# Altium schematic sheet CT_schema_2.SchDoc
size 289 x 230 mm
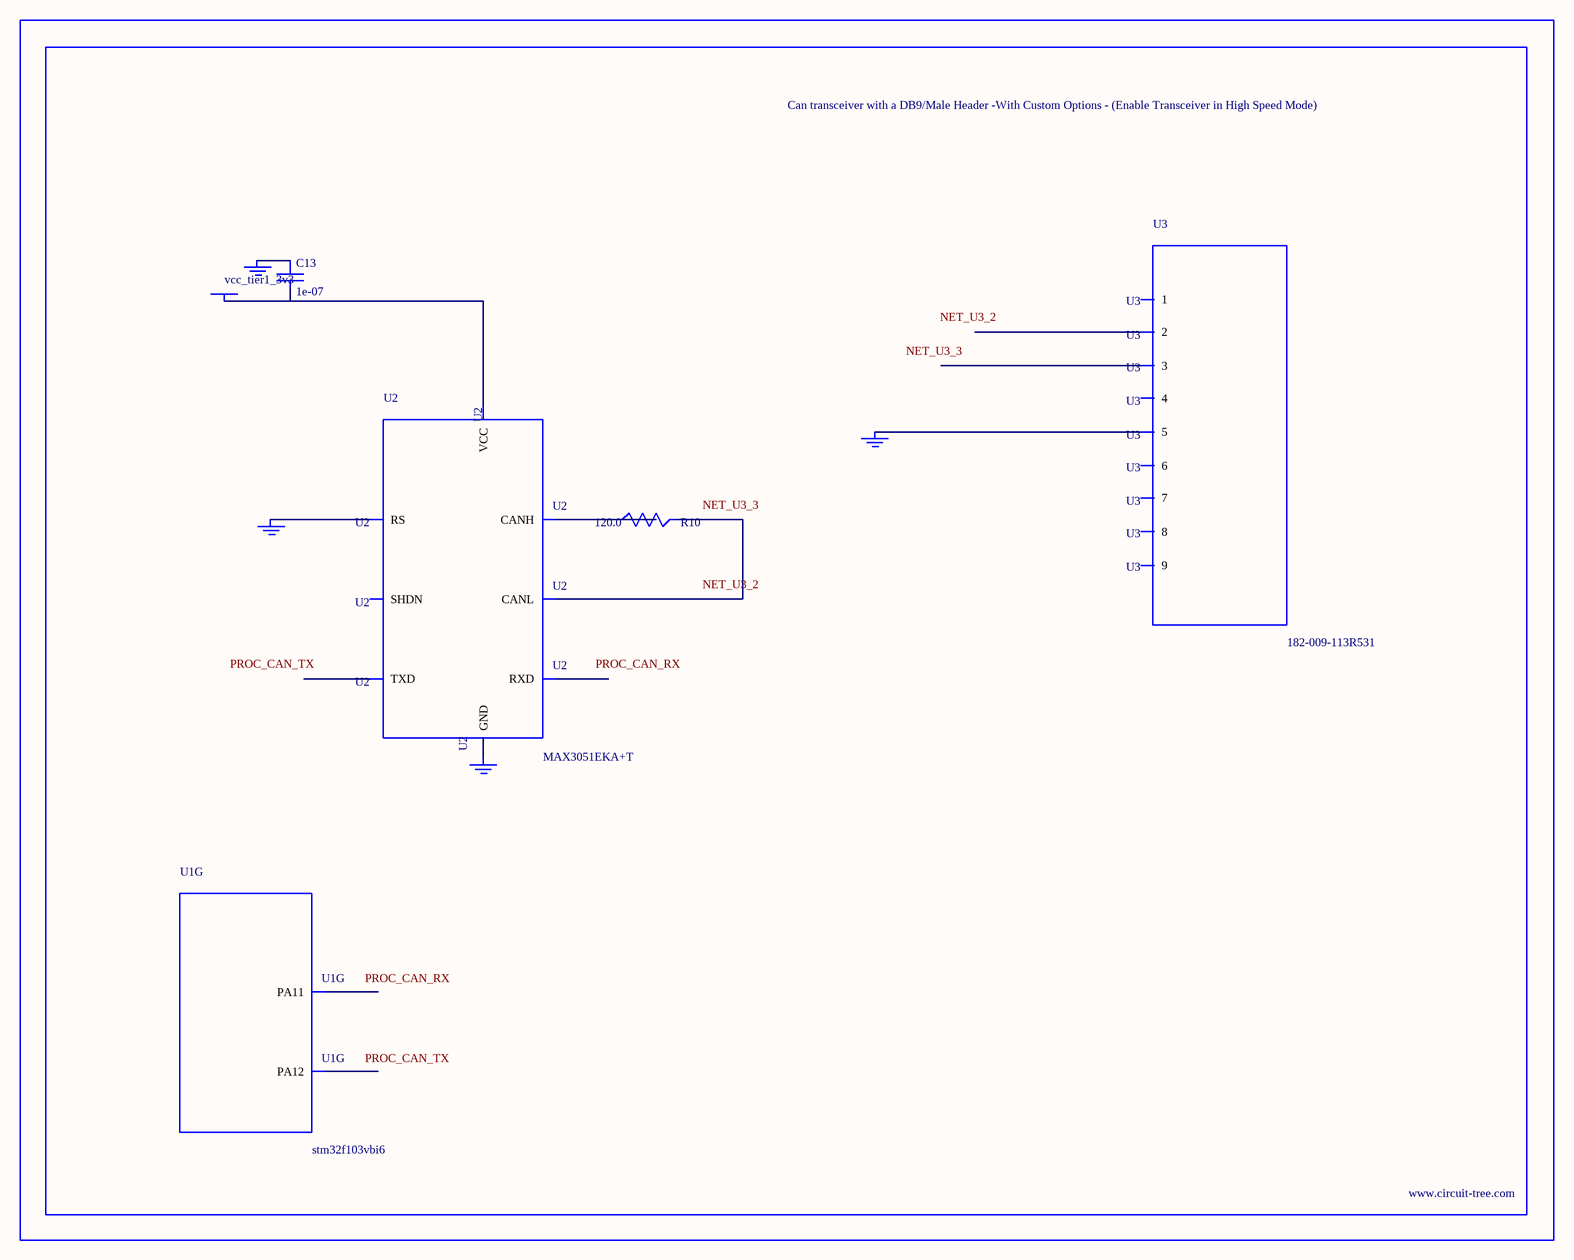
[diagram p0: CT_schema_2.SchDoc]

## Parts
BORDER1  (no value)
C13  1e-07  [C0402]
GND_INSTANCE_1_0  (no value)
GND_INSTANCE_1_1  (no value)
GND_INSTANCE_1_2  (no value)
GND_INSTANCE_1_3  (no value)
POWER_INSTANCE_1_0  vcc_tier1_3v3
R10  120.0  [R0603]
U1  stm32f103vbi6  [UFBGA100]  (part G of 10)
U2  MAX3051EKA+T  [SOT-23-8]
U3  182-009-113R531  [182-009-MALE]

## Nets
NetC13_1: C13.1 GND_INSTANCE_1_0.0(GND)
NetC13_2: C13.2 POWER_INSTANCE_1_0.0(PWR) U2.3(VCC)
NetGND_INSTANCE_1_1_0: GND_INSTANCE_1_1.0(GND) U2.8(RS)
NetGND_INSTANCE_1_2_0: GND_INSTANCE_1_2.0(GND) U2.2(GND)
NetGND_INSTANCE_1_3_0: GND_INSTANCE_1_3.0(GND) U3.5
NetR10_1: R10.1 U2.7(CANH)
NetR10_2: R10.2 U2.6(CANL)

Not connected (* = marked no-connect by the designer): U1 A12(PA12) B12(PA11); U2 1(TXD) 4(RXD) 5(SHDN); U3 1 2 3 4 6 7 8 9

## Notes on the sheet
- Labels drawn without touching a wire or pin: NET_U3_2, NET_U3_3, PROC_CAN_RX, PROC_CAN_TX

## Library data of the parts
BORDER1 = BORDER_PAGE1
C13 = C0402C104K3RACTU
GND_INSTANCE_1_0-GND_INSTANCE_1_3 = GND
POWER_INSTANCE_1_0 = PWR
R10 = RC0603JR-07120RL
